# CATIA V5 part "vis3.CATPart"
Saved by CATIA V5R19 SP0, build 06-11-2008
Part number: vis3
Definition: NONE
Nomenclature: 1
Source: Unknown
Description: PART-1-DESC
Bounding box of the stored display mesh (mm): x -2.75 to 2.75, y -2.615 to 2.615, z -30 to 3
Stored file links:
  G:\EU_thinkMotion\CFAO_2010\MMS_groupe3\MMS_groupe3\A reprendre\ftixier\florent-tixier\florent-tixier\vis3.CATPart
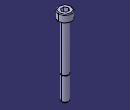
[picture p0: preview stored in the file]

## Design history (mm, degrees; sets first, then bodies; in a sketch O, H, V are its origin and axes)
Set1
  Sketch1 on zx-plane, origin (0, 0, 0), H (-1, 0, 0), V (0, 0, 1)
    circle A1 centre (1.5, -20.1) radius 0.1
    point P1 (1.5, -20.1)
    reference projected line E1 through (0, 0) direction (0, 1) from axis of face of Solid1
    distance A1 H = 20
    distance P1 E1 = 1.5
    radius A1 = 0.1
Body1 "1" (main body)
  Solid1: solid without history
  Groove1: profile Sketch1, axis axis of face of Solid1, angle 360
  Sketch2 on zx-plane, origin (0, 0, 0), H (-1, 0, 0), V (0, 0, 1)
    line L1 (-17.3169, -30) -> (22.6735, -30)
    line L2 (22.6735, -30) -> (22.6735, -60)
    line L3 (22.6735, -60) -> (-17.3169, -60)
    line L4 (-17.3169, -60) -> (-17.3169, -30)
    distance L1 H = 30
    length L2 = 30
    horizontal: L1 H, L3 H
    vertical: L2 V, L4 V
  Pocket1: profile Sketch2, direction (0, -1, 0), length 28, mirrored extent
  Chamfer1: length 0.2, angle 60, on edge [face of Pocket1 from Sketch2.L1 | face of Solid1]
